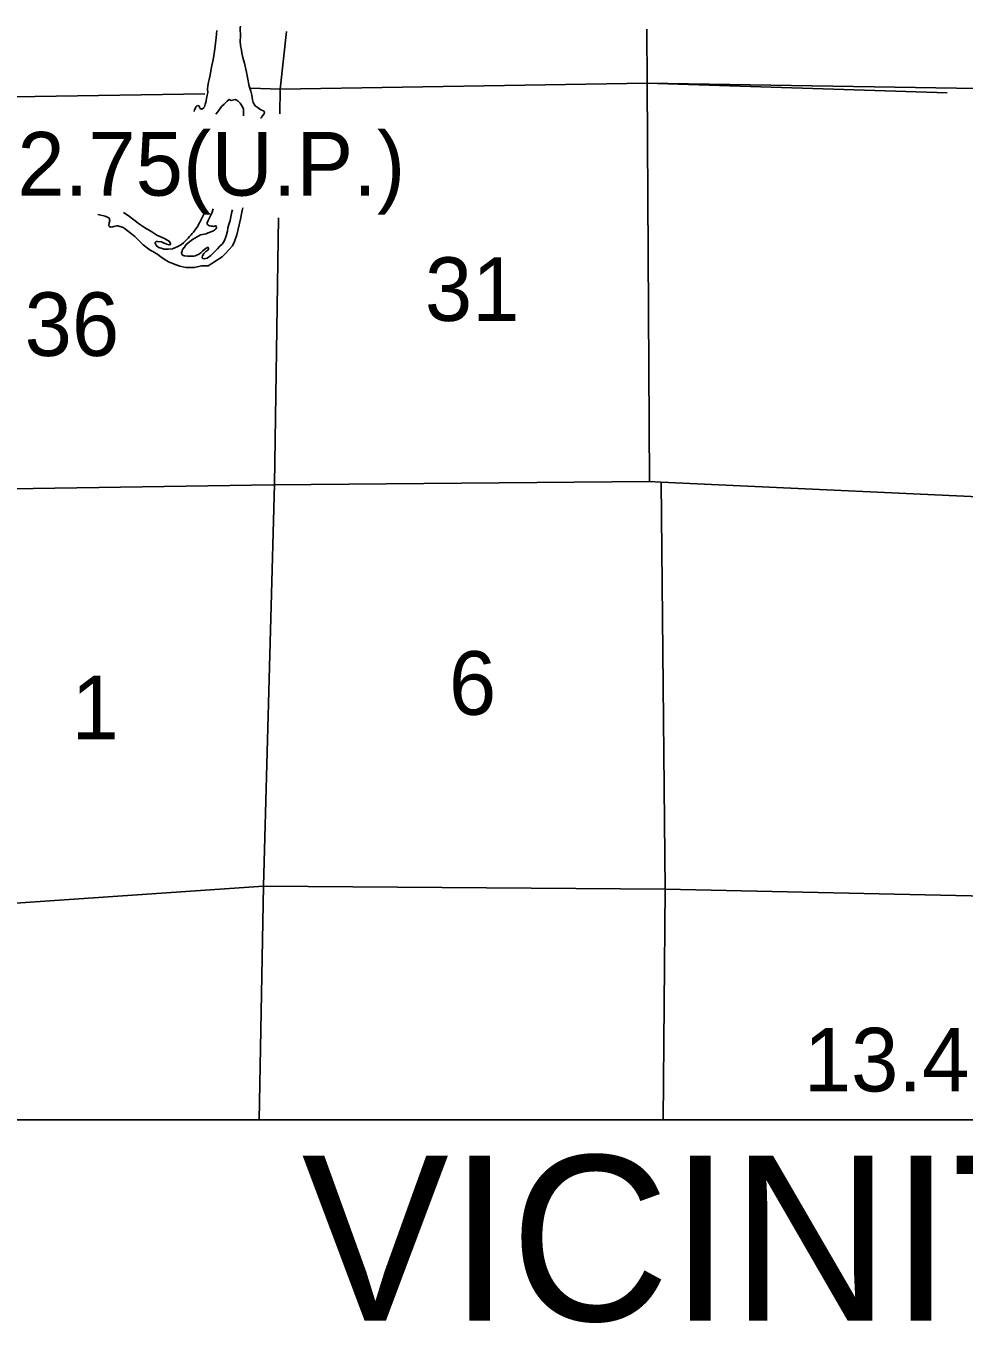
# Model space of a CAD drawing. Extents: x 22866 to 28196, y 1324810 to 1328105.
# Drawn here: x 24121.3 to 24328.3, y 1326608 to 1326894.3 of the extents above; entities that cross this region are included whole.
import ezdxf

# ---------------------------------------------------------------- set-up
doc = ezdxf.new("R2010")
doc.units = 0
for name, color, linetype in [('Default', 7, 'Continuous'), ('Level 4', 7, 'Continuous'), ('Level 5', 7, 'Continuous'), ('Level 58', 7, 'Continuous'), ('Level 9', 7, 'Continuous'), ('R_No Plot', 7, 'Continuous')]:
    doc.layers.add(name, color=color, linetype=linetype)

msp = doc.modelspace()

# ---------------------------------------------------------------- linework, layer by layer
at = {"layer": 'Level 4'}
for points in [[(24178.81, 1326893.07), (24177.44, 1326880.41), (24177.36, 1326874.9)], [(24178.81, 1326893.07), (24177.44, 1326880.41), (24177.36, 1326874.9)], [(24177.02, 1326852), (24176.16, 1326793.19), (24173.77, 1326704.47), (24172.78, 1326652.92)], [(24177.02, 1326852), (24176.16, 1326793.19), (24173.77, 1326704.47), (24172.78, 1326652.92)], [(24258.9, 1326793.76), (24175.93, 1326793.02), (24089.1, 1326791.75), (24078.02, 1326791.42)], [(24258.9, 1326793.76), (24175.93, 1326793.02), (24089.1, 1326791.75), (24078.02, 1326791.42)], [(24401.06, 1326789.93), (24350.14, 1326789.57), (24347.32, 1326789.69), (24261.52, 1326793.67), (24258.9, 1326793.76)], [(24401.06, 1326789.93), (24350.14, 1326789.57), (24347.32, 1326789.69), (24261.52, 1326793.67), (24258.9, 1326793.76)]]:
    msp.add_lwpolyline(points, dxfattribs=at)
at = {"layer": 'Level 5'}
for points in [[(24258.37, 1326893.64), (24258.44, 1326881.68), (24258.9, 1326793.76)], [(24258.37, 1326893.64), (24258.44, 1326881.68), (24258.9, 1326793.76)], [(24258.44, 1326881.68), (24177.44, 1326880.41), (24170.96, 1326880.62)], [(24258.44, 1326881.68), (24177.44, 1326880.41), (24170.96, 1326880.62)], [(24324.61, 1326879.55), (24258.44, 1326881.68)], [(24417.79, 1326879.11), (24258.44, 1326881.68)], [(24160.82, 1326879.36), (24090.42, 1326878.23), (24083.82, 1326878.24)], [(24160.82, 1326879.36), (24090.42, 1326878.23), (24083.82, 1326878.24)], [(24261.94, 1326652.92), (24262.38, 1326703.79), (24261.52, 1326793.67)], [(24261.94, 1326652.92), (24262.38, 1326703.79), (24261.52, 1326793.67)], [(24173.77, 1326704.47), (24085.79, 1326698.42), (24064.74, 1326698.57)], [(24173.77, 1326704.47), (24085.79, 1326698.42), (24064.74, 1326698.57)], [(24262.38, 1326703.79), (24173.77, 1326704.47)], [(24262.38, 1326703.79), (24173.77, 1326704.47)], [(24388.33, 1326700.99), (24350.13, 1326701.9), (24262.38, 1326703.79)], [(24388.33, 1326700.99), (24350.13, 1326701.9), (24262.38, 1326703.79)]]:
    msp.add_lwpolyline(points, dxfattribs=at)
at = {"layer": 'Level 9'}
for points in [[(24163.44, 1326893.29), (24163.4, 1326892.61), (24163.3, 1326891.74), (24163.15, 1326890.54), (24162.99, 1326889.31), (24162.83, 1326888.27), (24162.61, 1326886.84), (24162.36, 1326885.6), (24162.23, 1326884.9), (24161.94, 1326883.47), (24161.75, 1326882.5), (24161.62, 1326881.93), (24161.43, 1326881.13), (24161.41, 1326880.37), (24161.44, 1326879.67), (24161.32, 1326879.04), (24161.19, 1326878.34), (24161.06, 1326877.77), (24161, 1326877.47), (24160.9, 1326877.07), (24160.71, 1326876.47)], [(24163.44, 1326893.29), (24163.4, 1326892.61), (24163.3, 1326891.74), (24163.15, 1326890.54), (24162.99, 1326889.31), (24162.83, 1326888.27), (24162.61, 1326886.84), (24162.36, 1326885.6), (24162.23, 1326884.9), (24161.94, 1326883.47), (24161.75, 1326882.5), (24161.62, 1326881.93), (24161.43, 1326881.13), (24161.41, 1326880.37), (24161.44, 1326879.67), (24161.32, 1326879.04), (24161.19, 1326878.34), (24161.06, 1326877.77), (24161, 1326877.47), (24160.9, 1326877.07), (24160.71, 1326876.47)], [(24168.65, 1326894.28), (24168.63, 1326893.88), (24168.68, 1326891.98), (24168.62, 1326890.95), (24168.69, 1326890.05), (24168.87, 1326889.02), (24168.97, 1326888.36), (24169.21, 1326887.36), (24169.56, 1326886.13), (24169.8, 1326885.1), (24170.01, 1326884.1), (24170.21, 1326882.94), (24170.59, 1326881.05), (24170.97, 1326879.95), (24171.14, 1326879.02), (24171.32, 1326877.99), (24171.49, 1326877.42), (24171.66, 1326877.06), (24171.89, 1326876.73), (24172.33, 1326876.43), (24172.89, 1326876), (24173.16, 1326875.84), (24173.73, 1326875.58), (24173.96, 1326875.28), (24173.86, 1326874.91), (24173.47, 1326874.44), (24173.27, 1326874.14), (24173.1, 1326873.96)], [(24168.65, 1326894.28), (24168.63, 1326893.88), (24168.68, 1326891.98), (24168.62, 1326890.95), (24168.69, 1326890.05), (24168.87, 1326889.02), (24168.97, 1326888.36), (24169.21, 1326887.36), (24169.56, 1326886.13), (24169.8, 1326885.1), (24170.01, 1326884.1), (24170.21, 1326882.94), (24170.59, 1326881.05), (24170.97, 1326879.95), (24171.14, 1326879.02), (24171.32, 1326877.99), (24171.49, 1326877.42), (24171.66, 1326877.06), (24171.89, 1326876.73), (24172.33, 1326876.43), (24172.89, 1326876), (24173.16, 1326875.84), (24173.73, 1326875.58), (24173.96, 1326875.28), (24173.86, 1326874.91), (24173.47, 1326874.44), (24173.27, 1326874.14), (24173.1, 1326873.96)], [(24160.71, 1326876.47), (24160.51, 1326876.23), (24160.44, 1326876.13), (24160.35, 1326876.06), (24160.21, 1326876.03), (24160.11, 1326876), (24160.01, 1326875.99), (24159.71, 1326876.19), (24159.68, 1326876.26), (24159.65, 1326876.39), (24159.54, 1326876.66), (24159.48, 1326876.72), (24159.28, 1326876.79), (24159.24, 1326876.79), (24159.01, 1326876.69), (24158.81, 1326876.48), (24158.65, 1326876.05), (24158.55, 1326875.78), (24158.42, 1326875.51), (24158.41, 1326875.46)], [(24160.71, 1326876.47), (24160.51, 1326876.23), (24160.44, 1326876.13), (24160.35, 1326876.06), (24160.21, 1326876.03), (24160.11, 1326876), (24160.01, 1326875.99), (24159.71, 1326876.19), (24159.68, 1326876.26), (24159.65, 1326876.39), (24159.54, 1326876.66), (24159.48, 1326876.72), (24159.28, 1326876.79), (24159.24, 1326876.79), (24159.01, 1326876.69), (24158.81, 1326876.48), (24158.65, 1326876.05), (24158.55, 1326875.78), (24158.42, 1326875.51), (24158.41, 1326875.46)], [(24163.26, 1326874.89), (24163.67, 1326875.39), (24164.49, 1326876.53), (24165.05, 1326877.1), (24165.48, 1326877.51), (24165.74, 1326877.71), (24166.2, 1326878.11), (24166.6, 1326877.88), (24167.47, 1326878.06), (24167.7, 1326877.99), (24168.17, 1326877.7), (24168.63, 1326877.3), (24169.07, 1326876.64), (24169.31, 1326875.97), (24169.35, 1326874.74), (24169.32, 1326874.52)], [(24163.26, 1326874.89), (24163.67, 1326875.39), (24164.49, 1326876.53), (24165.05, 1326877.1), (24165.48, 1326877.51), (24165.74, 1326877.71), (24166.2, 1326878.11), (24166.6, 1326877.88), (24167.47, 1326878.06), (24167.7, 1326877.99), (24168.17, 1326877.7), (24168.63, 1326877.3), (24169.07, 1326876.64), (24169.31, 1326875.97), (24169.35, 1326874.74), (24169.32, 1326874.52)], [(24152.79, 1326842.3), (24151.79, 1326842.89), (24151.09, 1326843.35), (24150.42, 1326843.85), (24149.32, 1326844.54), (24148.72, 1326844.87), (24148.15, 1326845.26), (24147.21, 1326846.02), (24146.71, 1326846.51), (24146.18, 1326847.04), (24145.37, 1326847.83), (24144.6, 1326848.46), (24143.97, 1326848.99), (24143.27, 1326849.48), (24142.97, 1326849.71), (24142.77, 1326849.81), (24142.14, 1326850.07), (24142.07, 1326850.07), (24141.67, 1326850.2), (24141.27, 1326850.2), (24140.74, 1326850.06), (24140.48, 1326849.96), (24140.11, 1326849.92), (24139.88, 1326849.98), (24139.71, 1326850.08), (24139.61, 1326850.35), (24139.67, 1326850.71), (24139.71, 1326850.85), (24139.87, 1326851.38), (24139.7, 1326851.91), (24139.46, 1326852.04), (24138.83, 1326852.31), (24137.53, 1326852.66), (24137.22, 1326852.73)], [(24152.79, 1326842.3), (24151.79, 1326842.89), (24151.09, 1326843.35), (24150.42, 1326843.85), (24149.32, 1326844.54), (24148.72, 1326844.87), (24148.15, 1326845.26), (24147.21, 1326846.02), (24146.71, 1326846.51), (24146.18, 1326847.04), (24145.37, 1326847.83), (24144.6, 1326848.46), (24143.97, 1326848.99), (24143.27, 1326849.48), (24142.97, 1326849.71), (24142.77, 1326849.81), (24142.14, 1326850.07), (24142.07, 1326850.07), (24141.67, 1326850.2), (24141.27, 1326850.2), (24140.74, 1326850.06), (24140.48, 1326849.96), (24140.11, 1326849.92), (24139.88, 1326849.98), (24139.71, 1326850.08), (24139.61, 1326850.35), (24139.67, 1326850.71), (24139.71, 1326850.85), (24139.87, 1326851.38), (24139.7, 1326851.91), (24139.46, 1326852.04), (24138.83, 1326852.31), (24137.53, 1326852.66), (24137.22, 1326852.73)], [(24149.9, 1326846.21), (24149.87, 1326846.27), (24149.87, 1326846.44), (24149.93, 1326846.64), (24150.1, 1326846.81), (24150.29, 1326846.78), (24151.23, 1326846.65), (24151.82, 1326846.42), (24152.29, 1326846.23), (24152.36, 1326846.19), (24152.92, 1326846), (24152.96, 1326846), (24153.16, 1326846.1), (24153.25, 1326846.27), (24153.02, 1326846.77), (24151.92, 1326847.42), (24150.22, 1326848.17), (24149.08, 1326848.86), (24147.45, 1326849.88), (24146.41, 1326850.61), (24145.14, 1326851.53), (24143.87, 1326852.48), (24142.87, 1326853.14), (24142.84, 1326853.17)], [(24149.9, 1326846.21), (24149.87, 1326846.27), (24149.87, 1326846.44), (24149.93, 1326846.64), (24150.1, 1326846.81), (24150.29, 1326846.78), (24151.23, 1326846.65), (24151.82, 1326846.42), (24152.29, 1326846.23), (24152.36, 1326846.19), (24152.92, 1326846), (24152.96, 1326846), (24153.16, 1326846.1), (24153.25, 1326846.27), (24153.02, 1326846.77), (24151.92, 1326847.42), (24150.22, 1326848.17), (24149.08, 1326848.86), (24147.45, 1326849.88), (24146.41, 1326850.61), (24145.14, 1326851.53), (24143.87, 1326852.48), (24142.87, 1326853.14), (24142.84, 1326853.17)], [(24160.94, 1326853.99), (24160.92, 1326853.93), (24160.7, 1326853.09), (24160.37, 1326852.32), (24159.95, 1326851.49), (24159.62, 1326850.85), (24159.1, 1326849.95), (24158.84, 1326849.58), (24158.28, 1326848.84), (24158.02, 1326848.51), (24157.75, 1326848.24), (24157.39, 1326847.87), (24157.09, 1326847.47), (24156.8, 1326847.2), (24156.4, 1326846.76), (24156.11, 1326846.49), (24155.68, 1326846.09), (24154.85, 1326845.65), (24154.69, 1326845.58), (24154.32, 1326845.45), (24154.06, 1326845.31), (24153.99, 1326845.28), (24153.66, 1326845.17), (24152.7, 1326845.07), (24152.03, 1326845.09), (24151.77, 1326845.09), (24151.57, 1326845.16), (24151.17, 1326845.25), (24150.87, 1326845.35), (24150.67, 1326845.41), (24150.4, 1326845.55), (24150.34, 1326845.58), (24150.3, 1326845.64), (24150.14, 1326845.84), (24150.07, 1326845.94), (24149.9, 1326846.21)], [(24160.94, 1326853.99), (24160.92, 1326853.93), (24160.7, 1326853.09), (24160.37, 1326852.32), (24159.95, 1326851.49), (24159.62, 1326850.85), (24159.1, 1326849.95), (24158.84, 1326849.58), (24158.28, 1326848.84), (24158.02, 1326848.51), (24157.75, 1326848.24), (24157.39, 1326847.87), (24157.09, 1326847.47), (24156.8, 1326847.2), (24156.4, 1326846.76), (24156.11, 1326846.49), (24155.68, 1326846.09), (24154.85, 1326845.65), (24154.69, 1326845.58), (24154.32, 1326845.45), (24154.06, 1326845.31), (24153.99, 1326845.28), (24153.66, 1326845.17), (24152.7, 1326845.07), (24152.03, 1326845.09), (24151.77, 1326845.09), (24151.57, 1326845.16), (24151.17, 1326845.25), (24150.87, 1326845.35), (24150.67, 1326845.41), (24150.4, 1326845.55), (24150.34, 1326845.58), (24150.3, 1326845.64), (24150.14, 1326845.84), (24150.07, 1326845.94), (24149.9, 1326846.21)], [(24169.15, 1326854.19), (24169.03, 1326853.56), (24168.64, 1326851.7), (24168.16, 1326849.46), (24167.88, 1326848.19), (24167.36, 1326846.72), (24166.93, 1326845.79), (24166.08, 1326844.95), (24165.35, 1326844.08), (24164.63, 1326843.37), (24162.75, 1326842.16), (24162.12, 1326841.72), (24161.56, 1326841.41), (24160.1, 1326841.4), (24158.48, 1326840.99), (24156.62, 1326841.04), (24155.29, 1326841.33), (24154.45, 1326841.58), (24153.52, 1326841.94), (24152.79, 1326842.3)], [(24169.15, 1326854.19), (24169.03, 1326853.56), (24168.64, 1326851.7), (24168.16, 1326849.46), (24167.88, 1326848.19), (24167.36, 1326846.72), (24166.93, 1326845.79), (24166.08, 1326844.95), (24165.35, 1326844.08), (24164.63, 1326843.37), (24162.75, 1326842.16), (24162.12, 1326841.72), (24161.56, 1326841.41), (24160.1, 1326841.4), (24158.48, 1326840.99), (24156.62, 1326841.04), (24155.29, 1326841.33), (24154.45, 1326841.58), (24153.52, 1326841.94), (24152.79, 1326842.3)], [(24159.88, 1326844.26), (24159.68, 1326844.09), (24159.38, 1326843.89), (24158.98, 1326843.72), (24158.75, 1326843.62), (24158.35, 1326843.55), (24158.09, 1326843.51), (24157.59, 1326843.51), (24157.46, 1326843.51), (24157.26, 1326843.51), (24156.96, 1326843.54), (24156.36, 1326843.57), (24156.23, 1326843.56), (24155.93, 1326843.73), (24155.8, 1326843.83), (24155.73, 1326843.93), (24155.69, 1326844.03), (24155.66, 1326844.16), (24155.66, 1326844.26), (24155.76, 1326844.59), (24155.89, 1326844.96), (24156.31, 1326845.53), (24156.71, 1326846.1), (24158.06, 1326847.21), (24158.62, 1326847.51), (24159.81, 1326848.26), (24161.07, 1326848.47), (24161.53, 1326848.64), (24162.59, 1326849.05), (24162.99, 1326849.35), (24163.22, 1326849.52), (24163.35, 1326849.79), (24163.31, 1326850.15), (24163.15, 1326850.22), (24162.68, 1326850.08), (24162.52, 1326850.11), (24162.38, 1326850.11), (24162.18, 1326850.17), (24161.88, 1326850.24), (24161.69, 1326850.27), (24161.55, 1326850.34), (24161.42, 1326850.5), (24161.32, 1326850.67), (24161.32, 1326850.73), (24161.32, 1326850.87), (24161.51, 1326851.4), (24162.07, 1326852.44), (24162.39, 1326853.24), (24162.61, 1326854)], [(24159.88, 1326844.26), (24159.68, 1326844.09), (24159.38, 1326843.89), (24158.98, 1326843.72), (24158.75, 1326843.62), (24158.35, 1326843.55), (24158.09, 1326843.51), (24157.59, 1326843.51), (24157.46, 1326843.51), (24157.26, 1326843.51), (24156.96, 1326843.54), (24156.36, 1326843.57), (24156.23, 1326843.56), (24155.93, 1326843.73), (24155.8, 1326843.83), (24155.73, 1326843.93), (24155.69, 1326844.03), (24155.66, 1326844.16), (24155.66, 1326844.26), (24155.76, 1326844.59), (24155.89, 1326844.96), (24156.31, 1326845.53), (24156.71, 1326846.1), (24158.06, 1326847.21), (24158.62, 1326847.51), (24159.81, 1326848.26), (24161.07, 1326848.47), (24161.53, 1326848.64), (24162.59, 1326849.05), (24162.99, 1326849.35), (24163.22, 1326849.52), (24163.35, 1326849.79), (24163.31, 1326850.15), (24163.15, 1326850.22), (24162.68, 1326850.08), (24162.52, 1326850.11), (24162.38, 1326850.11), (24162.18, 1326850.17), (24161.88, 1326850.24), (24161.69, 1326850.27), (24161.55, 1326850.34), (24161.42, 1326850.5), (24161.32, 1326850.67), (24161.32, 1326850.73), (24161.32, 1326850.87), (24161.51, 1326851.4), (24162.07, 1326852.44), (24162.39, 1326853.24), (24162.61, 1326854)], [(24166.87, 1326853.76), (24166.77, 1326853.28), (24166.55, 1326852.21), (24166.36, 1326851.41), (24166.13, 1326850.54), (24165.91, 1326849.74), (24165.78, 1326849.07), (24165.65, 1326848.51), (24165.52, 1326847.97), (24165.39, 1326847.54), (24165.13, 1326846.94), (24164.67, 1326846.23), (24164.11, 1326845.7), (24163.62, 1326845.16), (24163.03, 1326844.55), (24162.1, 1326843.65), (24161.31, 1326843.08), (24160.62, 1326842.94), (24160.35, 1326843), (24160.25, 1326843.1), (24160.22, 1326843.3), (24160.28, 1326843.6), (24160.57, 1326844.07), (24160.8, 1326844.3), (24161.04, 1326844.54), (24161.46, 1326844.87), (24161.6, 1326845.04), (24161.59, 1326845.24), (24161.53, 1326845.47), (24161.26, 1326845.37), (24160.86, 1326845.17), (24160.27, 1326844.6), (24159.88, 1326844.26)], [(24166.87, 1326853.76), (24166.77, 1326853.28), (24166.55, 1326852.21), (24166.36, 1326851.41), (24166.13, 1326850.54), (24165.91, 1326849.74), (24165.78, 1326849.07), (24165.65, 1326848.51), (24165.52, 1326847.97), (24165.39, 1326847.54), (24165.13, 1326846.94), (24164.67, 1326846.23), (24164.11, 1326845.7), (24163.62, 1326845.16), (24163.03, 1326844.55), (24162.1, 1326843.65), (24161.31, 1326843.08), (24160.62, 1326842.94), (24160.35, 1326843), (24160.25, 1326843.1), (24160.22, 1326843.3), (24160.28, 1326843.6), (24160.57, 1326844.07), (24160.8, 1326844.3), (24161.04, 1326844.54), (24161.46, 1326844.87), (24161.6, 1326845.04), (24161.59, 1326845.24), (24161.53, 1326845.47), (24161.26, 1326845.37), (24160.86, 1326845.17), (24160.27, 1326844.6), (24159.88, 1326844.26)]]:
    msp.add_lwpolyline(points, dxfattribs=at)
at = {"layer": 'R_No Plot'}
msp.add_lwpolyline([(23932.69, 1327446.26), (24728.44, 1327446.26), (24728.44, 1326652.92), (23932.69, 1326652.92)], close=True, dxfattribs=at)

# ---------------------------------------------------------------- texts
at = {"layer": 'Default'}
msp.add_text('VICINITY MAP', height=36.436, dxfattribs=at).set_placement((24182.16, 1326608.55))
at = {"layer": 'Level 5'}
for s, height, p in [('31', 14.044, (24209.36, 1326829.22)), ('31', 14.044, (24209.36, 1326829.22)), ('36', 14.044, (24121.02, 1326821.49)), ('36', 14.044, (24121.02, 1326821.49)), ('6', 14.04, (24214.67, 1326742.29)), ('6', 14.04, (24214.67, 1326742.29)), ('1', 14.04, (24131.39, 1326736.87)), ('1', 14.04, (24131.39, 1326736.87))]:
    msp.add_text(s, height=height, dxfattribs=at).set_placement(p)
at = {"layer": 'Level 58'}
for s, height, p in [('92.75(U.P.)', 14.0442, (24108.99, 1326856.88)), ('92.75(U.P.)', 14.0442, (24108.99, 1326856.88)), ('13.48', 14.044, (24292.97, 1326659.15)), ('13.48', 14.044, (24292.97, 1326659.15))]:
    msp.add_text(s, height=height, dxfattribs=at).set_placement(p)

doc.saveas('drawing.dxf')
